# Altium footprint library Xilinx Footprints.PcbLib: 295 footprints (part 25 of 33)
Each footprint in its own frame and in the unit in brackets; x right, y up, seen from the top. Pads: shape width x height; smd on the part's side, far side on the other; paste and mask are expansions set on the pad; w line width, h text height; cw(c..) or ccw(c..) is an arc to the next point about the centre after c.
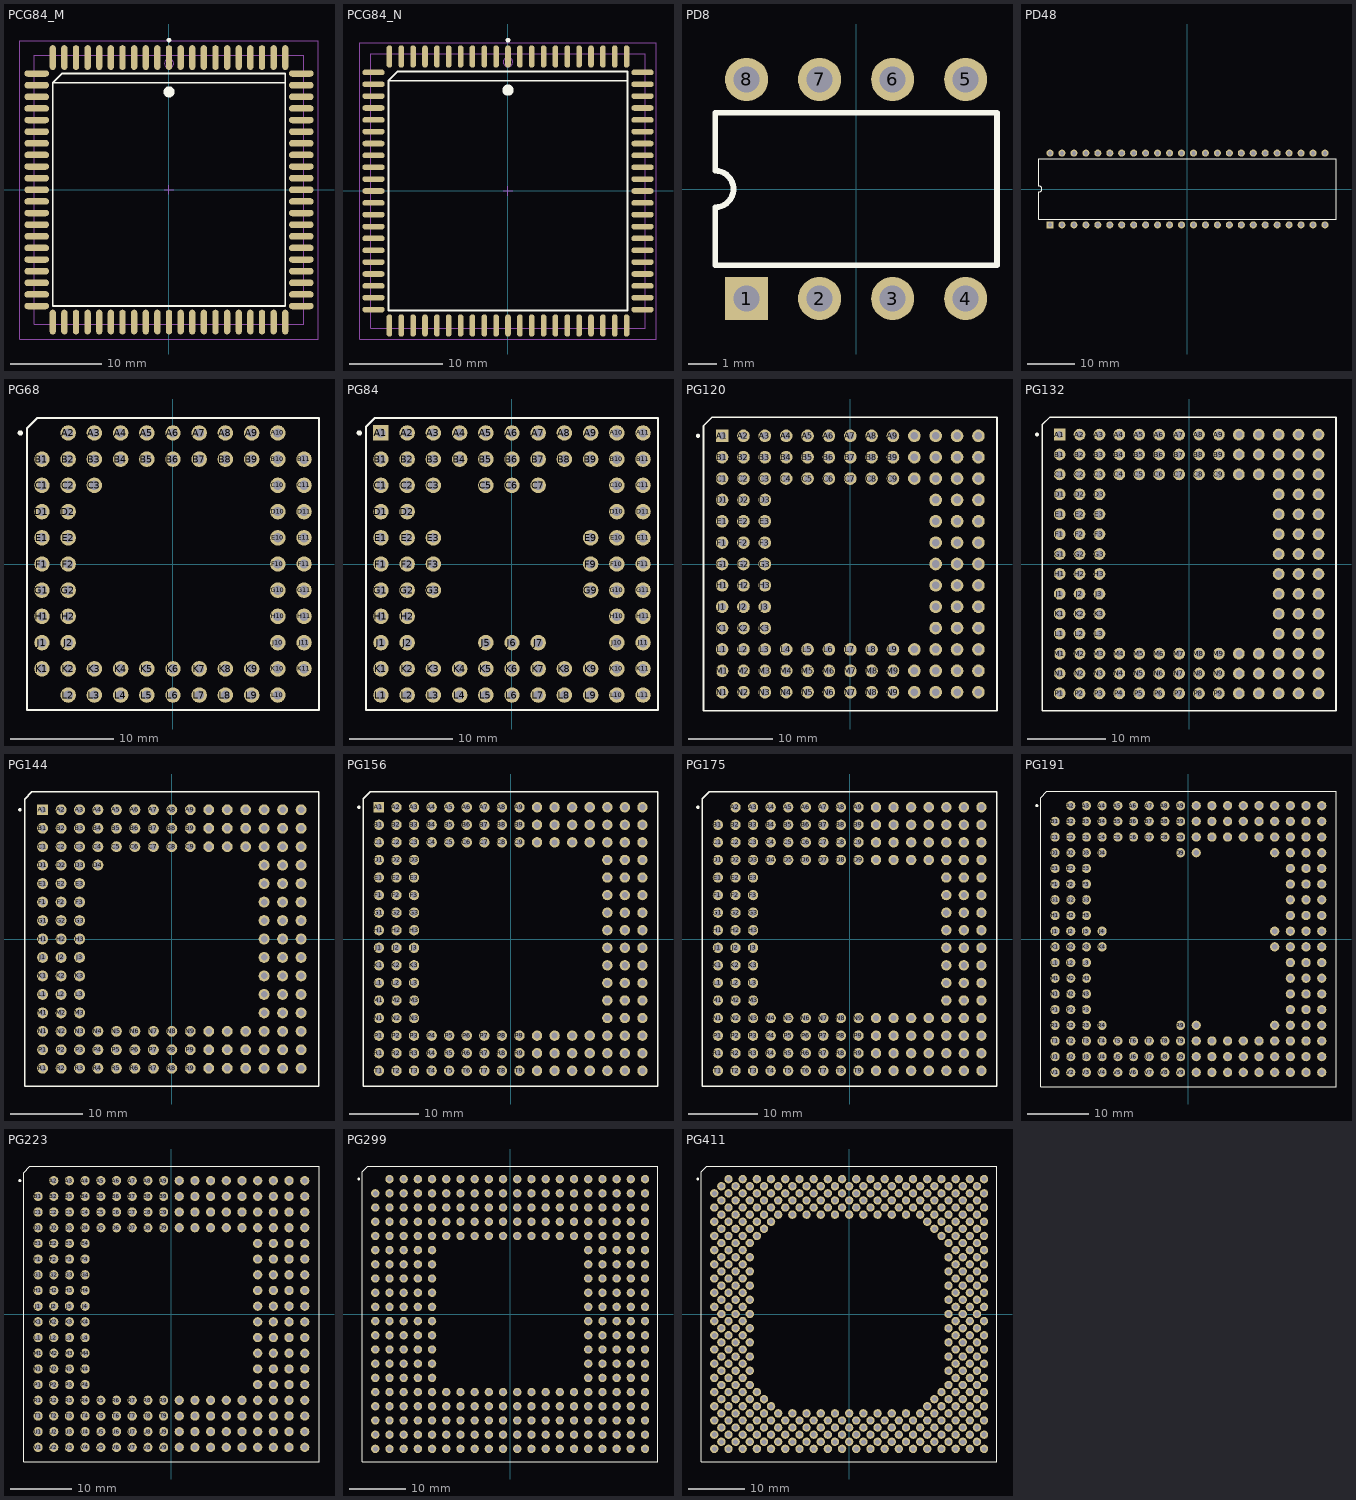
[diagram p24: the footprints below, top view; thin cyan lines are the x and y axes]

## PCG84_M [mm] "84-Pin Plastic Leaded Chip Carrier (PCG84) - Pb-Free, IPC Low Density"
height 5.08
pads (84):
  oval 0.7x2.7 smd: 1(0,14.45) 2(-1.27,14.45) 3(-2.54,14.45) 4(-3.81,14.45) 5(-5.08,14.45) 6(-6.35,14.45) 7(-7.62,14.45) 8(-8.89,14.45) 9(-10.16,14.45) 10(-11.43,14.45) 11(-12.7,14.45) 33(-12.7,-14.45) 34(-11.43,-14.45) 35(-10.16,-14.45) 36(-8.89,-14.45) 37(-7.62,-14.45) 38(-6.35,-14.45) 39(-5.08,-14.45) 40(-3.81,-14.45) 41(-2.54,-14.45) 42(-1.27,-14.45) 43(0,-14.45) 44(1.27,-14.45) 45(2.54,-14.45) 46(3.81,-14.45) 47(5.08,-14.45) 48(6.35,-14.45) 49(7.62,-14.45) 50(8.89,-14.45) 51(10.16,-14.45) 52(11.43,-14.45) 53(12.7,-14.45) 75(12.7,14.45) 76(11.43,14.45) 77(10.16,14.45) 78(8.89,14.45) 79(7.62,14.45) 80(6.35,14.45) 81(5.08,14.45) 82(3.81,14.45) 83(2.54,14.45) 84(1.27,14.45)
  oval 2.7x0.7 smd: 12(-14.45,12.7) 13(-14.45,11.43) 14(-14.45,10.16) 15(-14.45,8.89) 16(-14.45,7.62) 17(-14.45,6.35) 18(-14.45,5.08) 19(-14.45,3.81) 20(-14.45,2.54) 21(-14.45,1.27) 22(-14.45,0) 23(-14.45,-1.27) 24(-14.45,-2.54) 25(-14.45,-3.81) 26(-14.45,-5.08) 27(-14.45,-6.35) 28(-14.45,-7.62) 29(-14.45,-8.89) 30(-14.45,-10.16) 31(-14.45,-11.43) 32(-14.45,-12.7) 54(14.45,-12.7) 55(14.45,-11.43) 56(14.45,-10.16) 57(14.45,-8.89) 58(14.45,-7.62) 59(14.45,-6.35) 60(14.45,-5.08) 61(14.45,-3.81) 62(14.45,-2.54) 63(14.45,-1.27) 64(14.45,0) 65(14.45,1.27) 66(14.45,2.54) 67(14.45,3.81) 68(14.45,5.08) 69(14.45,6.35) 70(14.45,7.62) 71(14.45,8.89) 72(14.45,10.16) 73(14.45,11.43) 74(14.45,12.7)
Top Overlay:
  circle w0.25: c0,16.35 r0.125
  circle w0.6: c0,10.7 r0.3
  lines w0.2: 12.7,11.7 -12.7,11.7 ; -12.7,11.7 -11.7,12.7 12.7,12.7 12.7,-12.7 -12.7,-12.7 -12.7,11.7
Mechanical 13:
  circle w0.1: c0,13.805 r0.5
  lines w0.1: -14.705,-14.705 -14.705,14.705 14.705,14.705 14.705,-14.705 -14.705,-14.705
Mechanical 15:
  lines w0.1: -0.5,0 0.5,0 ; 0,-0.5 0,0.5 ; -16.3,-16.3 -16.3,16.3 16.3,16.3 16.3,-16.3 -16.3,-16.3
3D body: height 5.08, standoff 0, extent -14.705,-14.705 14.705,14.705

## PCG84_N [mm] "84-Pin Plastic Leaded Chip Carrier (PCG84) - Pb-Free, IPC Medium Density"
height 5.08
pads (84):
  oval 0.6x2.4 smd: 1(0,14.4) 2(-1.27,14.4) 3(-2.54,14.4) 4(-3.81,14.4) 5(-5.08,14.4) 6(-6.35,14.4) 7(-7.62,14.4) 8(-8.89,14.4) 9(-10.16,14.4) 10(-11.43,14.4) 11(-12.7,14.4) 33(-12.7,-14.4) 34(-11.43,-14.4) 35(-10.16,-14.4) 36(-8.89,-14.4) 37(-7.62,-14.4) 38(-6.35,-14.4) 39(-5.08,-14.4) 40(-3.81,-14.4) 41(-2.54,-14.4) 42(-1.27,-14.4) 43(0,-14.4) 44(1.27,-14.4) 45(2.54,-14.4) 46(3.81,-14.4) 47(5.08,-14.4) 48(6.35,-14.4) 49(7.62,-14.4) 50(8.89,-14.4) 51(10.16,-14.4) 52(11.43,-14.4) 53(12.7,-14.4) 75(12.7,14.4) 76(11.43,14.4) 77(10.16,14.4) 78(8.89,14.4) 79(7.62,14.4) 80(6.35,14.4) 81(5.08,14.4) 82(3.81,14.4) 83(2.54,14.4) 84(1.27,14.4)
  oval 2.4x0.6 smd: 12(-14.4,12.7) 13(-14.4,11.43) 14(-14.4,10.16) 15(-14.4,8.89) 16(-14.4,7.62) 17(-14.4,6.35) 18(-14.4,5.08) 19(-14.4,3.81) 20(-14.4,2.54) 21(-14.4,1.27) 22(-14.4,0) 23(-14.4,-1.27) 24(-14.4,-2.54) 25(-14.4,-3.81) 26(-14.4,-5.08) 27(-14.4,-6.35) 28(-14.4,-7.62) 29(-14.4,-8.89) 30(-14.4,-10.16) 31(-14.4,-11.43) 32(-14.4,-12.7) 54(14.4,-12.7) 55(14.4,-11.43) 56(14.4,-10.16) 57(14.4,-8.89) 58(14.4,-7.62) 59(14.4,-6.35) 60(14.4,-5.08) 61(14.4,-3.81) 62(14.4,-2.54) 63(14.4,-1.27) 64(14.4,0) 65(14.4,1.27) 66(14.4,2.54) 67(14.4,3.81) 68(14.4,5.08) 69(14.4,6.35) 70(14.4,7.62) 71(14.4,8.89) 72(14.4,10.16) 73(14.4,11.43) 74(14.4,12.7)
Top Overlay:
  circle w0.25: c0,16.15 r0.125
  circle w0.6: c0,10.8 r0.3
  lines w0.2: 12.8,11.8 -12.8,11.8 ; -12.8,11.8 -11.8,12.8 12.8,12.8 12.8,-12.8 -12.8,-12.8 -12.8,11.8
Mechanical 13:
  circle w0.1: c0,13.805 r0.5
  lines w0.1: -14.705,-14.705 -14.705,14.705 14.705,14.705 14.705,-14.705 -14.705,-14.705
Mechanical 15:
  lines w0.1: -0.5,0 0.5,0 ; 0,-0.5 0,0.5 ; -15.85,-15.85 -15.85,15.85 15.85,15.85 15.85,-15.85 -15.85,-15.85
3D body: height 5.08, standoff 0, extent -14.705,-14.705 14.705,14.705

## PD8 [mm] "8-Pin Plastic DIP (PD8)"
height 4.6
pads (8):
  rect 1.5x1.5 hole 0.9: 1(-3.81,-3.81)
  round 1.5 hole 0.9: 2(-1.27,-3.81) 3(1.27,-3.81) 4(3.81,-3.81) 5(3.81,3.81) 6(1.27,3.81) 7(-1.27,3.81) 8(-3.81,3.81)
Top Overlay:
  lines w0.2: -4.9,-2.65 -4.9,-0.635 ccw(c-4.9,0) -4.9,0.635 -4.9,2.65 4.9,2.65 4.9,-2.65 -4.9,-2.65

## PD48 [mm] "48-Pin Plastic DIP (PD48)"
height 4.83
pads (48):
  rect 1.5x1.5 hole 0.9: 1(-29.21,-7.62)
  round 1.5 hole 0.9: 2(-26.67,-7.62) 3(-24.13,-7.62) 4(-21.59,-7.62) 5(-19.05,-7.62) 6(-16.51,-7.62) 7(-13.97,-7.62) 8(-11.43,-7.62) 9(-8.89,-7.62) 10(-6.35,-7.62) 11(-3.81,-7.62) 12(-1.27,-7.62) 13(1.27,-7.62) 14(3.81,-7.62) 15(6.35,-7.62) 16(8.89,-7.62) 17(11.43,-7.62) 18(13.97,-7.62) 19(16.51,-7.62) 20(19.05,-7.62) 21(21.59,-7.62) 22(24.13,-7.62) 23(26.67,-7.62) 24(29.21,-7.62) 25(29.21,7.62) 26(26.67,7.62) 27(24.13,7.62) 28(21.59,7.62) 29(19.05,7.62) 30(16.51,7.62) 31(13.97,7.62) 32(11.43,7.62) 33(8.89,7.62) 34(6.35,7.62) 35(3.81,7.62) 36(1.27,7.62) 37(-1.27,7.62) 38(-3.81,7.62) 39(-6.35,7.62) 40(-8.89,7.62) 41(-11.43,7.62) 42(-13.97,7.62) 43(-16.51,7.62) 44(-19.05,7.62) 45(-21.59,7.62) 46(-24.13,7.62) 47(-26.67,7.62) 48(-29.21,7.62)
Top Overlay:
  lines w0.2: -31.55,-6.45 31.55,-6.45 31.55,6.45 -31.55,6.45 -31.55,0.635 cw(c-31.55,0) -31.55,-0.635 -31.55,-6.45

## PG68 [mm] "68-Pin Ceramic Pin Grid Array (PG68)"
height 5.21
pads (69):
  round 1.5 hole 0.9: A2(-10.16,12.7) A3(-7.62,12.7) A4(-5.08,12.7) A5(-2.54,12.7) A6(0,12.7) A7(2.54,12.7) A8(5.08,12.7) A9(7.62,12.7) A10(10.16,12.7) B1(-12.7,10.16) B2(-10.16,10.16) B3(-7.62,10.16) B4(-5.08,10.16) B5(-2.54,10.16) B6(0,10.16) B7(2.54,10.16) B8(5.08,10.16) B9(7.62,10.16) B10(10.16,10.16) B11(12.7,10.16) C1(-12.7,7.62) C2(-10.16,7.62) C3(-7.62,7.62) C10(10.16,7.62) C11(12.7,7.62) D1(-12.7,5.08) D2(-10.16,5.08) D10(10.16,5.08) D11(12.7,5.08) E1(-12.7,2.54) E2(-10.16,2.54) E10(10.16,2.54) E11(12.7,2.54) F1(-12.7,0) F2(-10.16,0) F10(10.16,0) F11(12.7,0) G1(-12.7,-2.54) G2(-10.16,-2.54) G10(10.16,-2.54) G11(12.7,-2.54) H1(-12.7,-5.08) H2(-10.16,-5.08) H10(10.16,-5.08) H11(12.7,-5.08) J1(-12.7,-7.62) J2(-10.16,-7.62) J10(10.16,-7.62) J11(12.7,-7.62) K1(-12.7,-10.16) K2(-10.16,-10.16) K3(-7.62,-10.16) K4(-5.08,-10.16) K5(-2.54,-10.16) K6(0,-10.16) K7(2.54,-10.16) K8(5.08,-10.16) K9(7.62,-10.16) K10(10.16,-10.16) K11(12.7,-10.16) L2(-10.16,-12.7) L3(-7.62,-12.7) L4(-5.08,-12.7) L5(-2.54,-12.7) L6(0,-12.7) L7(2.54,-12.7) L8(5.08,-12.7) L9(7.62,-12.7) L10(10.16,-12.7)
Top Overlay:
  circle w0.25: c-14.8,12.7 r0.125
  lines w0.2: -14.15,-14.15 -14.15,13.15 -13.15,14.15 14.15,14.15 14.15,-14.15 -14.15,-14.15

## PG84 [mm] "84-Pin Ceramic Pin Grid Array (PG84)"
height 5.21
pads (85):
  rect 1.5x1.5 hole 0.9: A1(-12.7,12.7)
  round 1.5 hole 0.9: A2(-10.16,12.7) A3(-7.62,12.7) A4(-5.08,12.7) A5(-2.54,12.7) A6(0,12.7) A7(2.54,12.7) A8(5.08,12.7) A9(7.62,12.7) A10(10.16,12.7) A11(12.7,12.7) B1(-12.7,10.16) B2(-10.16,10.16) B3(-7.62,10.16) B4(-5.08,10.16) B5(-2.54,10.16) B6(0,10.16) B7(2.54,10.16) B8(5.08,10.16) B9(7.62,10.16) B10(10.16,10.16) B11(12.7,10.16) C1(-12.7,7.62) C2(-10.16,7.62) C3(-7.62,7.62) C5(-2.54,7.62) C6(0,7.62) C7(2.54,7.62) C10(10.16,7.62) C11(12.7,7.62) D1(-12.7,5.08) D2(-10.16,5.08) D10(10.16,5.08) D11(12.7,5.08) E1(-12.7,2.54) E2(-10.16,2.54) E3(-7.62,2.54) E9(7.62,2.54) E10(10.16,2.54) E11(12.7,2.54) F1(-12.7,0) F2(-10.16,0) F3(-7.62,0) F9(7.62,0) F10(10.16,0) F11(12.7,0) G1(-12.7,-2.54) G2(-10.16,-2.54) G3(-7.62,-2.54) G9(7.62,-2.54) G10(10.16,-2.54) G11(12.7,-2.54) H1(-12.7,-5.08) H2(-10.16,-5.08) H10(10.16,-5.08) H11(12.7,-5.08) J1(-12.7,-7.62) J2(-10.16,-7.62) J5(-2.54,-7.62) J6(0,-7.62) J7(2.54,-7.62) J10(10.16,-7.62) J11(12.7,-7.62) K1(-12.7,-10.16) K2(-10.16,-10.16) K3(-7.62,-10.16) K4(-5.08,-10.16) K5(-2.54,-10.16) K6(0,-10.16) K7(2.54,-10.16) K8(5.08,-10.16) K9(7.62,-10.16) K10(10.16,-10.16) K11(12.7,-10.16) L1(-12.7,-12.7) L2(-10.16,-12.7) L3(-7.62,-12.7) L4(-5.08,-12.7) L5(-2.54,-12.7) L6(0,-12.7) L7(2.54,-12.7) L8(5.08,-12.7) L9(7.62,-12.7) L10(10.16,-12.7) L11(12.7,-12.7)
Top Overlay:
  circle w0.25: c-14.8,12.7 r0.125
  lines w0.2: -14.15,-14.15 -14.15,13.316 -13.316,14.15 14.15,14.15 14.15,-14.15 -14.15,-14.15

## PG120 [mm] "120-Pin Ceramic Pin Grid Array (PG120)"
height 5.21
pads (120):
  rect 1.5x1.5 hole 0.9: A1(-15.24,15.24)
  round 1.5 hole 0.9: A2(-12.7,15.24) A3(-10.16,15.24) A4(-7.62,15.24) A5(-5.08,15.24) A6(-2.54,15.24) A7(0,15.24) A8(2.54,15.24) A9(5.08,15.24) A10(7.62,15.24) A11(10.16,15.24) A12(12.7,15.24) A13(15.24,15.24) B1(-15.24,12.7) B2(-12.7,12.7) B3(-10.16,12.7) B4(-7.62,12.7) B5(-5.08,12.7) B6(-2.54,12.7) B7(0,12.7) B8(2.54,12.7) B9(5.08,12.7) B10(7.62,12.7) B11(10.16,12.7) B12(12.7,12.7) B13(15.24,12.7) C1(-15.24,10.16) C2(-12.7,10.16) C3(-10.16,10.16) C4(-7.62,10.16) C5(-5.08,10.16) C6(-2.54,10.16) C7(0,10.16) C8(2.54,10.16) C9(5.08,10.16) C10(7.62,10.16) C11(10.16,10.16) C12(12.7,10.16) C13(15.24,10.16) D1(-15.24,7.62) D2(-12.7,7.62) D3(-10.16,7.62) D11(10.16,7.62) D12(12.7,7.62) D13(15.24,7.62) E1(-15.24,5.08) E2(-12.7,5.08) E3(-10.16,5.08) E11(10.16,5.08) E12(12.7,5.08) E13(15.24,5.08) F1(-15.24,2.54) F2(-12.7,2.54) F3(-10.16,2.54) F11(10.16,2.54) F12(12.7,2.54) F13(15.24,2.54) G1(-15.24,0) G2(-12.7,0) G3(-10.16,0) G11(10.16,0) G12(12.7,0) G13(15.24,0) H1(-15.24,-2.54) H2(-12.7,-2.54) H3(-10.16,-2.54) H11(10.16,-2.54) H12(12.7,-2.54) H13(15.24,-2.54) J1(-15.24,-5.08) J2(-12.7,-5.08) J3(-10.16,-5.08) J11(10.16,-5.08) J12(12.7,-5.08) J13(15.24,-5.08) K1(-15.24,-7.62) K2(-12.7,-7.62) K3(-10.16,-7.62) K11(10.16,-7.62) K12(12.7,-7.62) K13(15.24,-7.62) L1(-15.24,-10.16) L2(-12.7,-10.16) L3(-10.16,-10.16) L4(-7.62,-10.16) L5(-5.08,-10.16) L6(-2.54,-10.16) L7(0,-10.16) L8(2.54,-10.16) L9(5.08,-10.16) L10(7.62,-10.16) L11(10.16,-10.16) L12(12.7,-10.16) L13(15.24,-10.16) M1(-15.24,-12.7) M2(-12.7,-12.7) M3(-10.16,-12.7) M4(-7.62,-12.7) M5(-5.08,-12.7) M6(-2.54,-12.7) M7(0,-12.7) M8(2.54,-12.7) M9(5.08,-12.7) M10(7.62,-12.7) M11(10.16,-12.7) M12(12.7,-12.7) M13(15.24,-12.7) N1(-15.24,-15.24) N2(-12.7,-15.24) N3(-10.16,-15.24) N4(-7.62,-15.24) N5(-5.08,-15.24) N6(-2.54,-15.24) N7(0,-15.24) N8(2.54,-15.24) N9(5.08,-15.24) N10(7.62,-15.24) N11(10.16,-15.24) N12(12.7,-15.24) N13(15.24,-15.24)
Top Overlay:
  circle w0.25: c-18.1,15.24 r0.125
  lines w0.2: -17.45,-17.45 17.45,-17.45 17.45,17.45 -16.45,17.45 -17.45,16.45 -17.45,-17.45

## PG132 [mm] "132-Pin Ceramic Pin Grid Array (PG132)"
height 5.21
pads (132):
  rect 1.5x1.5 hole 0.9: A1(-16.51,16.51)
  round 1.5 hole 0.9: A2(-13.97,16.51) A3(-11.43,16.51) A4(-8.89,16.51) A5(-6.35,16.51) A6(-3.81,16.51) A7(-1.27,16.51) A8(1.27,16.51) A9(3.81,16.51) A10(6.35,16.51) A11(8.89,16.51) A12(11.43,16.51) A13(13.97,16.51) A14(16.51,16.51) B1(-16.51,13.97) B2(-13.97,13.97) B3(-11.43,13.97) B4(-8.89,13.97) B5(-6.35,13.97) B6(-3.81,13.97) B7(-1.27,13.97) B8(1.27,13.97) B9(3.81,13.97) B10(6.35,13.97) B11(8.89,13.97) B12(11.43,13.97) B13(13.97,13.97) B14(16.51,13.97) C1(-16.51,11.43) C2(-13.97,11.43) C3(-11.43,11.43) C4(-8.89,11.43) C5(-6.35,11.43) C6(-3.81,11.43) C7(-1.27,11.43) C8(1.27,11.43) C9(3.81,11.43) C10(6.35,11.43) C11(8.89,11.43) C12(11.43,11.43) C13(13.97,11.43) C14(16.51,11.43) D1(-16.51,8.89) D2(-13.97,8.89) D3(-11.43,8.89) D12(11.43,8.89) D13(13.97,8.89) D14(16.51,8.89) E1(-16.51,6.35) E2(-13.97,6.35) E3(-11.43,6.35) E12(11.43,6.35) E13(13.97,6.35) E14(16.51,6.35) F1(-16.51,3.81) F2(-13.97,3.81) F3(-11.43,3.81) F12(11.43,3.81) F13(13.97,3.81) F14(16.51,3.81) G1(-16.51,1.27) G2(-13.97,1.27) G3(-11.43,1.27) G12(11.43,1.27) G13(13.97,1.27) G14(16.51,1.27) H1(-16.51,-1.27) H2(-13.97,-1.27) H3(-11.43,-1.27) H12(11.43,-1.27) H13(13.97,-1.27) H14(16.51,-1.27) J1(-16.51,-3.81) J2(-13.97,-3.81) J3(-11.43,-3.81) J12(11.43,-3.81) J13(13.97,-3.81) J14(16.51,-3.81) K1(-16.51,-6.35) K2(-13.97,-6.35) K3(-11.43,-6.35) K12(11.43,-6.35) K13(13.97,-6.35) K14(16.51,-6.35) L1(-16.51,-8.89) L2(-13.97,-8.89) L3(-11.43,-8.89) L12(11.43,-8.89) L13(13.97,-8.89) L14(16.51,-8.89) M1(-16.51,-11.43) M2(-13.97,-11.43) M3(-11.43,-11.43) M4(-8.89,-11.43) M5(-6.35,-11.43) M6(-3.81,-11.43) M7(-1.27,-11.43) M8(1.27,-11.43) M9(3.81,-11.43) M10(6.35,-11.43) M11(8.89,-11.43) M12(11.43,-11.43) M13(13.97,-11.43) M14(16.51,-11.43) N1(-16.51,-13.97) N2(-13.97,-13.97) N3(-11.43,-13.97) N4(-8.89,-13.97) N5(-6.35,-13.97) N6(-3.81,-13.97) N7(-1.27,-13.97) N8(1.27,-13.97) N9(3.81,-13.97) N10(6.35,-13.97) N11(8.89,-13.97) N12(11.43,-13.97) N13(13.97,-13.97) N14(16.51,-13.97) P1(-16.51,-16.51) P2(-13.97,-16.51) P3(-11.43,-16.51) P4(-8.89,-16.51) P5(-6.35,-16.51) P6(-3.81,-16.51) P7(-1.27,-16.51) P8(1.27,-16.51) P9(3.81,-16.51) P10(6.35,-16.51) P11(8.89,-16.51) P12(11.43,-16.51) P13(13.97,-16.51) P14(16.51,-16.51)
Top Overlay:
  circle w0.25: c-19.4,16.51 r0.125
  lines w0.2: -18.75,-18.75 -18.75,17.75 -17.75,18.75 18.75,18.75 18.75,-18.75 -18.75,-18.75

## PG144 [mm] "144-Pin Ceramic Pin Grid Array (PG144)"
height 4.93
pads (145):
  rect 1.5x1.5 hole 0.9: A1(-17.78,17.78)
  round 1.5 hole 0.9: A2(-15.24,17.78) A3(-12.7,17.78) A4(-10.16,17.78) A5(-7.62,17.78) A6(-5.08,17.78) A7(-2.54,17.78) A8(0,17.78) A9(2.54,17.78) A10(5.08,17.78) A11(7.62,17.78) A12(10.16,17.78) A13(12.7,17.78) A14(15.24,17.78) A15(17.78,17.78) B1(-17.78,15.24) B2(-15.24,15.24) B3(-12.7,15.24) B4(-10.16,15.24) B5(-7.62,15.24) B6(-5.08,15.24) B7(-2.54,15.24) B8(0,15.24) B9(2.54,15.24) B10(5.08,15.24) B11(7.62,15.24) B12(10.16,15.24) B13(12.7,15.24) B14(15.24,15.24) B15(17.78,15.24) C1(-17.78,12.7) C2(-15.24,12.7) C3(-12.7,12.7) C4(-10.16,12.7) C5(-7.62,12.7) C6(-5.08,12.7) C7(-2.54,12.7) C8(0,12.7) C9(2.54,12.7) C10(5.08,12.7) C11(7.62,12.7) C12(10.16,12.7) C13(12.7,12.7) C14(15.24,12.7) C15(17.78,12.7) D1(-17.78,10.16) D2(-15.24,10.16) D3(-12.7,10.16) D4(-10.16,10.16) D13(12.7,10.16) D14(15.24,10.16) D15(17.78,10.16) E1(-17.78,7.62) E2(-15.24,7.62) E3(-12.7,7.62) E13(12.7,7.62) E14(15.24,7.62) E15(17.78,7.62) F1(-17.78,5.08) F2(-15.24,5.08) F3(-12.7,5.08) F13(12.7,5.08) F14(15.24,5.08) F15(17.78,5.08) G1(-17.78,2.54) G2(-15.24,2.54) G3(-12.7,2.54) G13(12.7,2.54) G14(15.24,2.54) G15(17.78,2.54) H1(-17.78,0) H2(-15.24,0) H3(-12.7,0) H13(12.7,0) H14(15.24,0) H15(17.78,0) J1(-17.78,-2.54) J2(-15.24,-2.54) J3(-12.7,-2.54) J13(12.7,-2.54) J14(15.24,-2.54) J15(17.78,-2.54) K1(-17.78,-5.08) K2(-15.24,-5.08) K3(-12.7,-5.08) K13(12.7,-5.08) K14(15.24,-5.08) K15(17.78,-5.08) L1(-17.78,-7.62) L2(-15.24,-7.62) L3(-12.7,-7.62) L13(12.7,-7.62) L14(15.24,-7.62) L15(17.78,-7.62) M1(-17.78,-10.16) M2(-15.24,-10.16) M3(-12.7,-10.16) M13(12.7,-10.16) M14(15.24,-10.16) M15(17.78,-10.16) N1(-17.78,-12.7) N2(-15.24,-12.7) N3(-12.7,-12.7) N4(-10.16,-12.7) N5(-7.62,-12.7) N6(-5.08,-12.7) N7(-2.54,-12.7) N8(0,-12.7) N9(2.54,-12.7) N10(5.08,-12.7) N11(7.62,-12.7) N12(10.16,-12.7) N13(12.7,-12.7) N14(15.24,-12.7) N15(17.78,-12.7) P1(-17.78,-15.24) P2(-15.24,-15.24) P3(-12.7,-15.24) P4(-10.16,-15.24) P5(-7.62,-15.24) P6(-5.08,-15.24) P7(-2.54,-15.24) P8(0,-15.24) P9(2.54,-15.24) P10(5.08,-15.24) P11(7.62,-15.24) P12(10.16,-15.24) P13(12.7,-15.24) P14(15.24,-15.24) P15(17.78,-15.24) R1(-17.78,-17.78) R2(-15.24,-17.78) R3(-12.7,-17.78) R4(-10.16,-17.78) R5(-7.62,-17.78) R6(-5.08,-17.78) R7(-2.54,-17.78) R8(0,-17.78) R9(2.54,-17.78) R10(5.08,-17.78) R11(7.62,-17.78) R12(10.16,-17.78) R13(12.7,-17.78) R14(15.24,-17.78) R15(17.78,-17.78)
Top Overlay:
  circle w0.25: c-20.9,17.78 r0.125
  lines w0.2: -20.25,-20.25 20.25,-20.25 20.25,20.25 -19.25,20.25 -20.25,19.25 -20.25,-20.25

## PG156 [mm] "156-Pin Ceramic Pin Grid Array (PG156)"
height 3.94
pads (156):
  rect 1.5x1.5 hole 0.9: A1(-19.05,19.05)
  round 1.5 hole 0.9: A2(-16.51,19.05) A3(-13.97,19.05) A4(-11.43,19.05) A5(-8.89,19.05) A6(-6.35,19.05) A7(-3.81,19.05) A8(-1.27,19.05) A9(1.27,19.05) A10(3.81,19.05) A11(6.35,19.05) A12(8.89,19.05) A13(11.43,19.05) A14(13.97,19.05) A15(16.51,19.05) A16(19.05,19.05) B1(-19.05,16.51) B2(-16.51,16.51) B3(-13.97,16.51) B4(-11.43,16.51) B5(-8.89,16.51) B6(-6.35,16.51) B7(-3.81,16.51) B8(-1.27,16.51) B9(1.27,16.51) B10(3.81,16.51) B11(6.35,16.51) B12(8.89,16.51) B13(11.43,16.51) B14(13.97,16.51) B15(16.51,16.51) B16(19.05,16.51) C1(-19.05,13.97) C2(-16.51,13.97) C3(-13.97,13.97) C4(-11.43,13.97) C5(-8.89,13.97) C6(-6.35,13.97) C7(-3.81,13.97) C8(-1.27,13.97) C9(1.27,13.97) C10(3.81,13.97) C11(6.35,13.97) C12(8.89,13.97) C13(11.43,13.97) C14(13.97,13.97) C15(16.51,13.97) C16(19.05,13.97) D1(-19.05,11.43) D2(-16.51,11.43) D3(-13.97,11.43) D14(13.97,11.43) D15(16.51,11.43) D16(19.05,11.43) E1(-19.05,8.89) E2(-16.51,8.89) E3(-13.97,8.89) E14(13.97,8.89) E15(16.51,8.89) E16(19.05,8.89) F1(-19.05,6.35) F2(-16.51,6.35) F3(-13.97,6.35) F14(13.97,6.35) F15(16.51,6.35) F16(19.05,6.35) G1(-19.05,3.81) G2(-16.51,3.81) G3(-13.97,3.81) G14(13.97,3.81) G15(16.51,3.81) G16(19.05,3.81) H1(-19.05,1.27) H2(-16.51,1.27) H3(-13.97,1.27) H14(13.97,1.27) H15(16.51,1.27) H16(19.05,1.27) J1(-19.05,-1.27) J2(-16.51,-1.27) J3(-13.97,-1.27) J14(13.97,-1.27) J15(16.51,-1.27) J16(19.05,-1.27) K1(-19.05,-3.81) K2(-16.51,-3.81) K3(-13.97,-3.81) K14(13.97,-3.81) K15(16.51,-3.81) K16(19.05,-3.81) L1(-19.05,-6.35) L2(-16.51,-6.35) L3(-13.97,-6.35) L14(13.97,-6.35) L15(16.51,-6.35) L16(19.05,-6.35) M1(-19.05,-8.89) M2(-16.51,-8.89) M3(-13.97,-8.89) M14(13.97,-8.89) M15(16.51,-8.89) M16(19.05,-8.89) N1(-19.05,-11.43) N2(-16.51,-11.43) N3(-13.97,-11.43) N14(13.97,-11.43) N15(16.51,-11.43) N16(19.05,-11.43) P1(-19.05,-13.97) P2(-16.51,-13.97) P3(-13.97,-13.97) P4(-11.43,-13.97) P5(-8.89,-13.97) P6(-6.35,-13.97) P7(-3.81,-13.97) P8(-1.27,-13.97) P9(1.27,-13.97) P10(3.81,-13.97) P11(6.35,-13.97) P12(8.89,-13.97) P13(11.43,-13.97) P14(13.97,-13.97) P15(16.51,-13.97) P16(19.05,-13.97) R1(-19.05,-16.51) R2(-16.51,-16.51) R3(-13.97,-16.51) R4(-11.43,-16.51) R5(-8.89,-16.51) R6(-6.35,-16.51) R7(-3.81,-16.51) R8(-1.27,-16.51) R9(1.27,-16.51) R10(3.81,-16.51) R11(6.35,-16.51) R12(8.89,-16.51) R13(11.43,-16.51) R14(13.97,-16.51) R15(16.51,-16.51) R16(19.05,-16.51) T1(-19.05,-19.05) T2(-16.51,-19.05) T3(-13.97,-19.05) T4(-11.43,-19.05) T5(-8.89,-19.05) T6(-6.35,-19.05) T7(-3.81,-19.05) T8(-1.27,-19.05) T9(1.27,-19.05) T10(3.81,-19.05) T11(6.35,-19.05) T12(8.89,-19.05) T13(11.43,-19.05) T14(13.97,-19.05) T15(16.51,-19.05) T16(19.05,-19.05)
Top Overlay:
  circle w0.25: c-21.95,19.05 r0.125
  lines w0.2: -21.3,-21.3 21.3,-21.3 21.3,21.3 -20.3,21.3 -21.3,20.3 -21.3,-21.3

## PG175 [mm] "175-Pin Ceramic Pin Grid Array (PG175)"
height 5.21
pads (175):
  round 1.5 hole 0.9: A2(-16.51,19.05) A3(-13.97,19.05) A4(-11.43,19.05) A5(-8.89,19.05) A6(-6.35,19.05) A7(-3.81,19.05) A8(-1.27,19.05) A9(1.27,19.05) A10(3.81,19.05) A11(6.35,19.05) A12(8.89,19.05) A13(11.43,19.05) A14(13.97,19.05) A15(16.51,19.05) A16(19.05,19.05) B1(-19.05,16.51) B2(-16.51,16.51) B3(-13.97,16.51) B4(-11.43,16.51) B5(-8.89,16.51) B6(-6.35,16.51) B7(-3.81,16.51) B8(-1.27,16.51) B9(1.27,16.51) B10(3.81,16.51) B11(6.35,16.51) B12(8.89,16.51) B13(11.43,16.51) B14(13.97,16.51) B15(16.51,16.51) B16(19.05,16.51) C1(-19.05,13.97) C2(-16.51,13.97) C3(-13.97,13.97) C4(-11.43,13.97) C5(-8.89,13.97) C6(-6.35,13.97) C7(-3.81,13.97) C8(-1.27,13.97) C9(1.27,13.97) C10(3.81,13.97) C11(6.35,13.97) C12(8.89,13.97) C13(11.43,13.97) C14(13.97,13.97) C15(16.51,13.97) C16(19.05,13.97) D1(-19.05,11.43) D2(-16.51,11.43) D3(-13.97,11.43) D4(-11.43,11.43) D5(-8.89,11.43) D6(-6.35,11.43) D7(-3.81,11.43) D8(-1.27,11.43) D9(1.27,11.43) D10(3.81,11.43) D11(6.35,11.43) D12(8.89,11.43) D13(11.43,11.43) D14(13.97,11.43) D15(16.51,11.43) D16(19.05,11.43) E1(-19.05,8.89) E2(-16.51,8.89) E3(-13.97,8.89) E14(13.97,8.89) E15(16.51,8.89) E16(19.05,8.89) F1(-19.05,6.35) F2(-16.51,6.35) F3(-13.97,6.35) F14(13.97,6.35) F15(16.51,6.35) F16(19.05,6.35) G1(-19.05,3.81) G2(-16.51,3.81) G3(-13.97,3.81) G14(13.97,3.81) G15(16.51,3.81) G16(19.05,3.81) H1(-19.05,1.27) H2(-16.51,1.27) H3(-13.97,1.27) H14(13.97,1.27) H15(16.51,1.27) H16(19.05,1.27) J1(-19.05,-1.27) J2(-16.51,-1.27) J3(-13.97,-1.27) J14(13.97,-1.27) J15(16.51,-1.27) J16(19.05,-1.27) K1(-19.05,-3.81) K2(-16.51,-3.81) K3(-13.97,-3.81) K14(13.97,-3.81) K15(16.51,-3.81) K16(19.05,-3.81) L1(-19.05,-6.35) L2(-16.51,-6.35) L3(-13.97,-6.35) L14(13.97,-6.35) L15(16.51,-6.35) L16(19.05,-6.35) M1(-19.05,-8.89) M2(-16.51,-8.89) M3(-13.97,-8.89) M14(13.97,-8.89) M15(16.51,-8.89) M16(19.05,-8.89) N1(-19.05,-11.43) N2(-16.51,-11.43) N3(-13.97,-11.43) N4(-11.43,-11.43) N5(-8.89,-11.43) N6(-6.35,-11.43) N7(-3.81,-11.43) N8(-1.27,-11.43) N9(1.27,-11.43) N10(3.81,-11.43) N11(6.35,-11.43) N12(8.89,-11.43) N13(11.43,-11.43) N14(13.97,-11.43) N15(16.51,-11.43) N16(19.05,-11.43) P1(-19.05,-13.97) P2(-16.51,-13.97) P3(-13.97,-13.97) P4(-11.43,-13.97) P5(-8.89,-13.97) P6(-6.35,-13.97) P7(-3.81,-13.97) P8(-1.27,-13.97) P9(1.27,-13.97) P10(3.81,-13.97) P11(6.35,-13.97) P12(8.89,-13.97) P13(11.43,-13.97) P14(13.97,-13.97) P15(16.51,-13.97) P16(19.05,-13.97) R1(-19.05,-16.51) R2(-16.51,-16.51) R3(-13.97,-16.51) R4(-11.43,-16.51) R5(-8.89,-16.51) R6(-6.35,-16.51) R7(-3.81,-16.51) R8(-1.27,-16.51) R9(1.27,-16.51) R10(3.81,-16.51) R11(6.35,-16.51) R12(8.89,-16.51) R13(11.43,-16.51) R14(13.97,-16.51) R15(16.51,-16.51) R16(19.05,-16.51) T1(-19.05,-19.05) T2(-16.51,-19.05) T3(-13.97,-19.05) T4(-11.43,-19.05) T5(-8.89,-19.05) T6(-6.35,-19.05) T7(-3.81,-19.05) T8(-1.27,-19.05) T9(1.27,-19.05) T10(3.81,-19.05) T11(6.35,-19.05) T12(8.89,-19.05) T13(11.43,-19.05) T14(13.97,-19.05) T15(16.51,-19.05) T16(19.05,-19.05)
Top Overlay:
  circle w0.25: c-21.95,19.05 r0.125
  lines w0.2: -21.3,-21.3 -21.3,20.3 -20.3,21.3 21.3,21.3 21.3,-21.3 -21.3,-21.3

## PG191 [mm] "191-Pin Ceramic Pin Grid Array (PG191)"
height 5.21
pads (191):
  round 1.5 hole 0.9: A2(-19.05,21.59) A3(-16.51,21.59) A4(-13.97,21.59) A5(-11.43,21.59) A6(-8.89,21.59) A7(-6.35,21.59) A8(-3.81,21.59) A9(-1.27,21.59) A10(1.27,21.59) A11(3.81,21.59) A12(6.35,21.59) A13(8.89,21.59) A14(11.43,21.59) A15(13.97,21.59) A16(16.51,21.59) A17(19.05,21.59) A18(21.59,21.59) B1(-21.59,19.05) B2(-19.05,19.05) B3(-16.51,19.05) B4(-13.97,19.05) B5(-11.43,19.05) B6(-8.89,19.05) B7(-6.35,19.05) B8(-3.81,19.05) B9(-1.27,19.05) B10(1.27,19.05) B11(3.81,19.05) B12(6.35,19.05) B13(8.89,19.05) B14(11.43,19.05) B15(13.97,19.05) B16(16.51,19.05) B17(19.05,19.05) B18(21.59,19.05) C1(-21.59,16.51) C2(-19.05,16.51) C3(-16.51,16.51) C4(-13.97,16.51) C5(-11.43,16.51) C6(-8.89,16.51) C7(-6.35,16.51) C8(-3.81,16.51) C9(-1.27,16.51) C10(1.27,16.51) C11(3.81,16.51) C12(6.35,16.51) C13(8.89,16.51) C14(11.43,16.51) C15(13.97,16.51) C16(16.51,16.51) C17(19.05,16.51) C18(21.59,16.51) D1(-21.59,13.97) D2(-19.05,13.97) D3(-16.51,13.97) D4(-13.97,13.97) D9(-1.27,13.97) D10(1.27,13.97) D15(13.97,13.97) D16(16.51,13.97) D17(19.05,13.97) D18(21.59,13.97) E1(-21.59,11.43) E2(-19.05,11.43) E3(-16.51,11.43) E16(16.51,11.43) E17(19.05,11.43) E18(21.59,11.43) F1(-21.59,8.89) F2(-19.05,8.89) F3(-16.51,8.89) F16(16.51,8.89) F17(19.05,8.89) F18(21.59,8.89) G1(-21.59,6.35) G2(-19.05,6.35) G3(-16.51,6.35) G16(16.51,6.35) G17(19.05,6.35) G18(21.59,6.35) H1(-21.59,3.81) H2(-19.05,3.81) H3(-16.51,3.81) H16(16.51,3.81) H17(19.05,3.81) H18(21.59,3.81) J1(-21.59,1.27) J2(-19.05,1.27) J3(-16.51,1.27) J4(-13.97,1.27) J15(13.97,1.27) J16(16.51,1.27) J17(19.05,1.27) J18(21.59,1.27) K1(-21.59,-1.27) K2(-19.05,-1.27) K3(-16.51,-1.27) K4(-13.97,-1.27) K15(13.97,-1.27) K16(16.51,-1.27) K17(19.05,-1.27) K18(21.59,-1.27) L1(-21.59,-3.81) L2(-19.05,-3.81) L3(-16.51,-3.81) L16(16.51,-3.81) L17(19.05,-3.81) L18(21.59,-3.81) M1(-21.59,-6.35) M2(-19.05,-6.35) M3(-16.51,-6.35) M16(16.51,-6.35) M17(19.05,-6.35) M18(21.59,-6.35) N1(-21.59,-8.89) N2(-19.05,-8.89) N3(-16.51,-8.89) N16(16.51,-8.89) N17(19.05,-8.89) N18(21.59,-8.89) P1(-21.59,-11.43) P2(-19.05,-11.43) P3(-16.51,-11.43) P16(16.51,-11.43) P17(19.05,-11.43) P18(21.59,-11.43) R1(-21.59,-13.97) R2(-19.05,-13.97) R3(-16.51,-13.97) R4(-13.97,-13.97) R9(-1.27,-13.97) R10(1.27,-13.97) R15(13.97,-13.97) R16(16.51,-13.97) R17(19.05,-13.97) R18(21.59,-13.97) T1(-21.59,-16.51) T2(-19.05,-16.51) T3(-16.51,-16.51) T4(-13.97,-16.51) T5(-11.43,-16.51) T6(-8.89,-16.51) T7(-6.35,-16.51) T8(-3.81,-16.51) T9(-1.27,-16.51) T10(1.27,-16.51) T11(3.81,-16.51) T12(6.35,-16.51) T13(8.89,-16.51) T14(11.43,-16.51) T15(13.97,-16.51) T16(16.51,-16.51) T17(19.05,-16.51) T18(21.59,-16.51) U1(-21.59,-19.05) U2(-19.05,-19.05) U3(-16.51,-19.05) U4(-13.97,-19.05) U5(-11.43,-19.05) U6(-8.89,-19.05) U7(-6.35,-19.05) U8(-3.81,-19.05) U9(-1.27,-19.05) U10(1.27,-19.05) U11(3.81,-19.05) U12(6.35,-19.05) U13(8.89,-19.05) U14(11.43,-19.05) U15(13.97,-19.05) U16(16.51,-19.05) U17(19.05,-19.05) U18(21.59,-19.05) V1(-21.59,-21.59) V2(-19.05,-21.59) V3(-16.51,-21.59) V4(-13.97,-21.59) V5(-11.43,-21.59) V6(-8.89,-21.59) V7(-6.35,-21.59) V8(-3.81,-21.59) V9(-1.27,-21.59) V10(1.27,-21.59) V11(3.81,-21.59) V12(6.35,-21.59) V13(8.89,-21.59) V14(11.43,-21.59) V15(13.97,-21.59) V16(16.51,-21.59) V17(19.05,-21.59) V18(21.59,-21.59)
Top Overlay:
  circle w0.25: c-24.55,21.59 r0.125
  lines w0.2: -23.9,-23.9 23.9,-23.9 23.9,23.9 -22.9,23.9 -23.9,22.9 -23.9,-23.9

## PG223 [mm] "223-Pin Ceramic Pin Grid Array (PG223)"
height 5.21
pads (223):
  round 1.5 hole 0.9: A2(-19.05,21.59) A3(-16.51,21.59) A4(-13.97,21.59) A5(-11.43,21.59) A6(-8.89,21.59) A7(-6.35,21.59) A8(-3.81,21.59) A9(-1.27,21.59) A10(1.27,21.59) A11(3.81,21.59) A12(6.35,21.59) A13(8.89,21.59) A14(11.43,21.59) A15(13.97,21.59) A16(16.51,21.59) A17(19.05,21.59) A18(21.59,21.59) B1(-21.59,19.05) B2(-19.05,19.05) B3(-16.51,19.05) B4(-13.97,19.05) B5(-11.43,19.05) B6(-8.89,19.05) B7(-6.35,19.05) B8(-3.81,19.05) B9(-1.27,19.05) B10(1.27,19.05) B11(3.81,19.05) B12(6.35,19.05) B13(8.89,19.05) B14(11.43,19.05) B15(13.97,19.05) B16(16.51,19.05) B17(19.05,19.05) B18(21.59,19.05) C1(-21.59,16.51) C2(-19.05,16.51) C3(-16.51,16.51) C4(-13.97,16.51) C5(-11.43,16.51) C6(-8.89,16.51) C7(-6.35,16.51) C8(-3.81,16.51) C9(-1.27,16.51) C10(1.27,16.51) C11(3.81,16.51) C12(6.35,16.51) C13(8.89,16.51) C14(11.43,16.51) C15(13.97,16.51) C16(16.51,16.51) C17(19.05,16.51) C18(21.59,16.51) D1(-21.59,13.97) D2(-19.05,13.97) D3(-16.51,13.97) D4(-13.97,13.97) D5(-11.43,13.97) D6(-8.89,13.97) D7(-6.35,13.97) D8(-3.81,13.97) D9(-1.27,13.97) D10(1.27,13.97) D11(3.81,13.97) D12(6.35,13.97) D13(8.89,13.97) D14(11.43,13.97) D15(13.97,13.97) D16(16.51,13.97) D17(19.05,13.97) D18(21.59,13.97) E1(-21.59,11.43) E2(-19.05,11.43) E3(-16.51,11.43) E4(-13.97,11.43) E15(13.97,11.43) E16(16.51,11.43) E17(19.05,11.43) E18(21.59,11.43) F1(-21.59,8.89) F2(-19.05,8.89) F3(-16.51,8.89) F4(-13.97,8.89) F15(13.97,8.89) F16(16.51,8.89) F17(19.05,8.89) F18(21.59,8.89) G1(-21.59,6.35) G2(-19.05,6.35) G3(-16.51,6.35) G4(-13.97,6.35) G15(13.97,6.35) G16(16.51,6.35) G17(19.05,6.35) G18(21.59,6.35) H1(-21.59,3.81) H2(-19.05,3.81) H3(-16.51,3.81) H4(-13.97,3.81) H15(13.97,3.81) H16(16.51,3.81) H17(19.05,3.81) H18(21.59,3.81) J1(-21.59,1.27) J2(-19.05,1.27) J3(-16.51,1.27) J4(-13.97,1.27) J15(13.97,1.27) J16(16.51,1.27) J17(19.05,1.27) J18(21.59,1.27) K1(-21.59,-1.27) K2(-19.05,-1.27) K3(-16.51,-1.27) K4(-13.97,-1.27) K15(13.97,-1.27) K16(16.51,-1.27) K17(19.05,-1.27) K18(21.59,-1.27) L1(-21.59,-3.81) L2(-19.05,-3.81) L3(-16.51,-3.81) L4(-13.97,-3.81) L15(13.97,-3.81) L16(16.51,-3.81) L17(19.05,-3.81) L18(21.59,-3.81) M1(-21.59,-6.35) M2(-19.05,-6.35) M3(-16.51,-6.35) M4(-13.97,-6.35) M15(13.97,-6.35) M16(16.51,-6.35) M17(19.05,-6.35) M18(21.59,-6.35) N1(-21.59,-8.89) N2(-19.05,-8.89) N3(-16.51,-8.89) N4(-13.97,-8.89) N15(13.97,-8.89) N16(16.51,-8.89) N17(19.05,-8.89) N18(21.59,-8.89) P1(-21.59,-11.43) P2(-19.05,-11.43) P3(-16.51,-11.43) P4(-13.97,-11.43) P15(13.97,-11.43) P16(16.51,-11.43) P17(19.05,-11.43) P18(21.59,-11.43) R1(-21.59,-13.97) R2(-19.05,-13.97) R3(-16.51,-13.97) R4(-13.97,-13.97) R5(-11.43,-13.97) R6(-8.89,-13.97) R7(-6.35,-13.97) R8(-3.81,-13.97) R9(-1.27,-13.97) R10(1.27,-13.97) R11(3.81,-13.97) R12(6.35,-13.97) R13(8.89,-13.97) R14(11.43,-13.97) R15(13.97,-13.97) R16(16.51,-13.97) R17(19.05,-13.97) R18(21.59,-13.97) T1(-21.59,-16.51) T2(-19.05,-16.51) T3(-16.51,-16.51) T4(-13.97,-16.51) T5(-11.43,-16.51) T6(-8.89,-16.51) T7(-6.35,-16.51) T8(-3.81,-16.51) T9(-1.27,-16.51) T10(1.27,-16.51) T11(3.81,-16.51) T12(6.35,-16.51) T13(8.89,-16.51) T14(11.43,-16.51) T15(13.97,-16.51) T16(16.51,-16.51) T17(19.05,-16.51) T18(21.59,-16.51) U1(-21.59,-19.05) U2(-19.05,-19.05) U3(-16.51,-19.05) U4(-13.97,-19.05) U5(-11.43,-19.05) U6(-8.89,-19.05) U7(-6.35,-19.05) U8(-3.81,-19.05) U9(-1.27,-19.05) U10(1.27,-19.05) U11(3.81,-19.05) U12(6.35,-19.05) U13(8.89,-19.05) U14(11.43,-19.05) U15(13.97,-19.05) U16(16.51,-19.05) U17(19.05,-19.05) U18(21.59,-19.05) V1(-21.59,-21.59) V2(-19.05,-21.59) V3(-16.51,-21.59) V4(-13.97,-21.59) V5(-11.43,-21.59) V6(-8.89,-21.59) V7(-6.35,-21.59) V8(-3.81,-21.59) V9(-1.27,-21.59) V10(1.27,-21.59) V11(3.81,-21.59) V12(6.35,-21.59) V13(8.89,-21.59) V14(11.43,-21.59) V15(13.97,-21.59) V16(16.51,-21.59) V17(19.05,-21.59) V18(21.59,-21.59)
Top Overlay:
  circle w0.25: c-24.55,21.59 r0.125
  lines w0.2: -23.9,-23.9 23.9,-23.9 23.9,23.9 -22.9,23.9 -23.9,22.9 -23.9,-23.9

## PG299 [mm] "299-Pin Ceramic Pin Grid Array (PG299)"
height 5.21
pads (299):
  round 1.5 hole 0.9: A2(-21.59,24.13) A3(-19.05,24.13) A4(-16.51,24.13) A5(-13.97,24.13) A6(-11.43,24.13) A7(-8.89,24.13) A8(-6.35,24.13) A9(-3.81,24.13) A10(-1.27,24.13) A11(1.27,24.13) A12(3.81,24.13) A13(6.35,24.13) A14(8.89,24.13) A15(11.43,24.13) A16(13.97,24.13) A17(16.51,24.13) A18(19.05,24.13) A19(21.59,24.13) A20(24.13,24.13) B1(-24.13,21.59) B2(-21.59,21.59) B3(-19.05,21.59) B4(-16.51,21.59) B5(-13.97,21.59) B6(-11.43,21.59) B7(-8.89,21.59) B8(-6.35,21.59) B9(-3.81,21.59) B10(-1.27,21.59) B11(1.27,21.59) B12(3.81,21.59) B13(6.35,21.59) B14(8.89,21.59) B15(11.43,21.59) B16(13.97,21.59) B17(16.51,21.59) B18(19.05,21.59) B19(21.59,21.59) B20(24.13,21.59) C1(-24.13,19.05) C2(-21.59,19.05) C3(-19.05,19.05) C4(-16.51,19.05) C5(-13.97,19.05) C6(-11.43,19.05) C7(-8.89,19.05) C8(-6.35,19.05) C9(-3.81,19.05) C10(-1.27,19.05) C11(1.27,19.05) C12(3.81,19.05) C13(6.35,19.05) C14(8.89,19.05) C15(11.43,19.05) C16(13.97,19.05) C17(16.51,19.05) C18(19.05,19.05) C19(21.59,19.05) C20(24.13,19.05) D1(-24.13,16.51) D2(-21.59,16.51) D3(-19.05,16.51) D4(-16.51,16.51) D5(-13.97,16.51) D6(-11.43,16.51) D7(-8.89,16.51) D8(-6.35,16.51) D9(-3.81,16.51) D10(-1.27,16.51) D11(1.27,16.51) D12(3.81,16.51) D13(6.35,16.51) D14(8.89,16.51) D15(11.43,16.51) D16(13.97,16.51) D17(16.51,16.51) D18(19.05,16.51) D19(21.59,16.51) D20(24.13,16.51) E1(-24.13,13.97) E2(-21.59,13.97) E3(-19.05,13.97) E4(-16.51,13.97) E5(-13.97,13.97) E6(-11.43,13.97) E7(-8.89,13.97) E8(-6.35,13.97) E9(-3.81,13.97) E10(-1.27,13.97) E11(1.27,13.97) E12(3.81,13.97) E13(6.35,13.97) E14(8.89,13.97) E15(11.43,13.97) E16(13.97,13.97) E17(16.51,13.97) E18(19.05,13.97) E19(21.59,13.97) E20(24.13,13.97) F1(-24.13,11.43) F2(-21.59,11.43) F3(-19.05,11.43) F4(-16.51,11.43) F5(-13.97,11.43) F16(13.97,11.43) F17(16.51,11.43) F18(19.05,11.43) F19(21.59,11.43) F20(24.13,11.43) G1(-24.13,8.89) G2(-21.59,8.89) G3(-19.05,8.89) G4(-16.51,8.89) G5(-13.97,8.89) G16(13.97,8.89) G17(16.51,8.89) G18(19.05,8.89) G19(21.59,8.89) G20(24.13,8.89) H1(-24.13,6.35) H2(-21.59,6.35) H3(-19.05,6.35) H4(-16.51,6.35) H5(-13.97,6.35) H16(13.97,6.35) H17(16.51,6.35) H18(19.05,6.35) H19(21.59,6.35) H20(24.13,6.35) J1(-24.13,3.81) J2(-21.59,3.81) J3(-19.05,3.81) J4(-16.51,3.81) J5(-13.97,3.81) J16(13.97,3.81) J17(16.51,3.81) J18(19.05,3.81) J19(21.59,3.81) J20(24.13,3.81) K1(-24.13,1.27) K2(-21.59,1.27) K3(-19.05,1.27) K4(-16.51,1.27) K5(-13.97,1.27) K16(13.97,1.27) K17(16.51,1.27) K18(19.05,1.27) K19(21.59,1.27) K20(24.13,1.27) L1(-24.13,-1.27) L2(-21.59,-1.27) L3(-19.05,-1.27) L4(-16.51,-1.27) L5(-13.97,-1.27) L16(13.97,-1.27) L17(16.51,-1.27) L18(19.05,-1.27) L19(21.59,-1.27) L20(24.13,-1.27) M1(-24.13,-3.81) M2(-21.59,-3.81) M3(-19.05,-3.81) M4(-16.51,-3.81) M5(-13.97,-3.81) M16(13.97,-3.81) M17(16.51,-3.81) M18(19.05,-3.81) M19(21.59,-3.81) M20(24.13,-3.81) N1(-24.13,-6.35) N2(-21.59,-6.35) N3(-19.05,-6.35) N4(-16.51,-6.35) N5(-13.97,-6.35) N16(13.97,-6.35) N17(16.51,-6.35) N18(19.05,-6.35) N19(21.59,-6.35) N20(24.13,-6.35) P1(-24.13,-8.89) P2(-21.59,-8.89) P3(-19.05,-8.89) P4(-16.51,-8.89) P5(-13.97,-8.89) P16(13.97,-8.89) P17(16.51,-8.89) P18(19.05,-8.89) P19(21.59,-8.89) P20(24.13,-8.89) R1(-24.13,-11.43) R2(-21.59,-11.43) R3(-19.05,-11.43) R4(-16.51,-11.43) R5(-13.97,-11.43) R16(13.97,-11.43) R17(16.51,-11.43) R18(19.05,-11.43) R19(21.59,-11.43) R20(24.13,-11.43) T1(-24.13,-13.97) T2(-21.59,-13.97) T3(-19.05,-13.97) T4(-16.51,-13.97) T5(-13.97,-13.97) T6(-11.43,-13.97) T7(-8.89,-13.97) T8(-6.35,-13.97) T9(-3.81,-13.97) T10(-1.27,-13.97) T11(1.27,-13.97) T12(3.81,-13.97) T13(6.35,-13.97) T14(8.89,-13.97) T15(11.43,-13.97) T16(13.97,-13.97) T17(16.51,-13.97) T18(19.05,-13.97) T19(21.59,-13.97) T20(24.13,-13.97) U1(-24.13,-16.51) U2(-21.59,-16.51) U3(-19.05,-16.51) U4(-16.51,-16.51) U5(-13.97,-16.51) U6(-11.43,-16.51) U7(-8.89,-16.51) U8(-6.35,-16.51) U9(-3.81,-16.51) U10(-1.27,-16.51) U11(1.27,-16.51) U12(3.81,-16.51) U13(6.35,-16.51) U14(8.89,-16.51) U15(11.43,-16.51) U16(13.97,-16.51) U17(16.51,-16.51) U18(19.05,-16.51) U19(21.59,-16.51) U20(24.13,-16.51) V1(-24.13,-19.05) V2(-21.59,-19.05) V3(-19.05,-19.05) V4(-16.51,-19.05) V5(-13.97,-19.05) V6(-11.43,-19.05) V7(-8.89,-19.05) V8(-6.35,-19.05) V9(-3.81,-19.05) V10(-1.27,-19.05) V11(1.27,-19.05) V12(3.81,-19.05) V13(6.35,-19.05) V14(8.89,-19.05) V15(11.43,-19.05) V16(13.97,-19.05) V17(16.51,-19.05) V18(19.05,-19.05) V19(21.59,-19.05) V20(24.13,-19.05) W1(-24.13,-21.59) W2(-21.59,-21.59) W3(-19.05,-21.59) W4(-16.51,-21.59) W5(-13.97,-21.59) W6(-11.43,-21.59) W7(-8.89,-21.59) W8(-6.35,-21.59) W9(-3.81,-21.59) W10(-1.27,-21.59) W11(1.27,-21.59) W12(3.81,-21.59) W13(6.35,-21.59) W14(8.89,-21.59) W15(11.43,-21.59) W16(13.97,-21.59) W17(16.51,-21.59) W18(19.05,-21.59) W19(21.59,-21.59) W20(24.13,-21.59) X1(-24.13,-24.13) X2(-21.59,-24.13) X3(-19.05,-24.13) X4(-16.51,-24.13) X5(-13.97,-24.13) X6(-11.43,-24.13) X7(-8.89,-24.13) X8(-6.35,-24.13) X9(-3.81,-24.13) X10(-1.27,-24.13) X11(1.27,-24.13) X12(3.81,-24.13) X13(6.35,-24.13) X14(8.89,-24.13) X15(11.43,-24.13) X16(13.97,-24.13) X17(16.51,-24.13) X18(19.05,-24.13) X19(21.558,-24.142) X20(24.13,-24.13)
Top Overlay:
  circle w0.25: c-27.1,24.13 r0.125
  lines w0.2: -26.45,-26.45 26.45,-26.45 26.45,26.45 -25.45,26.45 -26.45,25.45 -26.45,-26.45

## PG411 [mm] "411-Pin Ceramic Pin Grid Array (PG411)"
height 5.86
pads (411):
  round 1.5 hole 0.9: A3(-21.59,24.13) A5(-19.05,24.13) A7(-16.51,24.13) A9(-13.97,24.13) A11(-11.43,24.13) A13(-8.89,24.13) A15(-6.35,24.13) A17(-3.81,24.13) A19(-1.27,24.13) A21(1.27,24.13) A23(3.81,24.13) A25(6.35,24.13) A27(8.89,24.13) A29(11.43,24.13) A31(13.97,24.13) A33(16.51,24.13) A35(19.05,24.13) A37(21.59,24.13) A39(24.13,24.13) AA1(-24.13,-1.27) AA3(-21.59,-1.27) AA5(-19.05,-1.27) AA35(19.05,-1.27) AA37(21.59,-1.27) AA39(24.13,-1.27) AB2(-22.86,-2.54) AB4(-20.32,-2.54) AB6(-17.78,-2.54) AB34(17.78,-2.54) AB36(20.32,-2.54) AB38(22.86,-2.54) AC1(-24.13,-3.81) AC3(-21.59,-3.81) AC5(-19.05,-3.81) AC35(19.05,-3.81) AC37(21.59,-3.81) AC39(24.13,-3.81) AD2(-22.86,-5.08) AD4(-20.32,-5.08) AD6(-17.78,-5.08) AD34(17.78,-5.08) AD36(20.32,-5.08) AD38(22.86,-5.08) AE1(-24.13,-6.35) AE3(-21.59,-6.35) AE5(-19.05,-6.35) AE35(19.05,-6.35) AE37(21.59,-6.35) AE39(24.13,-6.35) AF2(-22.86,-7.62) AF4(-20.32,-7.62) AF6(-17.78,-7.62) AF34(17.78,-7.62) AF36(20.32,-7.62) AF38(22.86,-7.62) AG1(-24.13,-8.89) AG3(-21.59,-8.89) AG5(-19.05,-8.89) AG35(19.05,-8.89) AG37(21.59,-8.89) AG39(24.13,-8.89) AH2(-22.86,-10.16) AH4(-20.32,-10.16) AH6(-17.78,-10.16) AH34(17.78,-10.16) AH36(20.32,-10.16) AH38(22.86,-10.16) AJ1(-24.13,-11.43) AJ3(-21.59,-11.43) AJ5(-19.05,-11.43) AJ35(19.05,-11.43) AJ37(21.59,-11.43) AJ39(24.13,-11.43) AK2(-22.86,-12.7) AK4(-20.32,-12.7) AK6(-17.78,-12.7) AK34(17.78,-12.7) AK36(20.32,-12.7) AK38(22.86,-12.7) AL1(-24.13,-13.97) AL3(-21.59,-13.97) AL5(-19.05,-13.97) AL7(-16.51,-13.97) AL33(16.51,-13.97) AL35(19.05,-13.97) AL37(21.59,-13.97) AL39(24.13,-13.97) AM2(-22.86,-15.24) AM4(-20.32,-15.24) AM6(-17.78,-15.24) AM8(-15.24,-15.24) AM32(15.24,-15.24) AM34(17.78,-15.24) AM36(20.32,-15.24) AM38(22.86,-15.24) AN1(-24.13,-16.51) AN3(-21.59,-16.51) AN5(-19.05,-16.51) AN7(-16.51,-16.51) AN9(-13.97,-16.51) AN31(13.97,-16.51) AN33(16.51,-16.51) AN35(19.05,-16.51) AN37(21.59,-16.51) AN39(24.13,-16.51) AP2(-22.86,-17.78) AP4(-20.32,-17.78) AP6(-17.78,-17.78) AP8(-15.24,-17.78) AP10(-12.7,-17.78) AP12(-10.16,-17.78) AP14(-7.62,-17.78) AP16(-5.08,-17.78) AP18(-2.54,-17.78) AP20(0,-17.78) AP22(2.54,-17.78) AP24(5.08,-17.78) AP26(7.62,-17.78) AP28(10.16,-17.78) AP30(12.7,-17.78) AP32(15.24,-17.78) AP34(17.78,-17.78) AP36(20.32,-17.78) AP38(22.86,-17.78) AR1(-24.13,-19.05) AR3(-21.59,-19.05) AR5(-19.05,-19.05) AR7(-16.51,-19.05) AR9(-13.97,-19.05) AR11(-11.43,-19.05) AR13(-8.89,-19.05) AR15(-6.35,-19.05) AR17(-3.81,-19.05) AR19(-1.27,-19.05) AR21(1.27,-19.05) AR23(3.81,-19.05) AR25(6.35,-19.05) AR27(8.89,-19.05) AR29(11.43,-19.05) AR31(13.97,-19.05) AR33(16.51,-19.05) AR35(19.05,-19.05) AR37(21.59,-19.05) AR39(24.13,-19.05) AT2(-22.86,-20.32) AT4(-20.32,-20.32) AT6(-17.78,-20.32) AT8(-15.24,-20.32) AT10(-12.7,-20.32) AT12(-10.16,-20.32) AT14(-7.62,-20.32) AT16(-5.08,-20.32) AT18(-2.54,-20.32) AT20(0,-20.32) AT22(2.54,-20.32) AT24(5.08,-20.32) AT26(7.62,-20.32) AT28(10.16,-20.32) AT30(12.7,-20.32) AT32(15.24,-20.32) AT34(17.78,-20.32) AT36(20.32,-20.32) AT38(22.86,-20.32) AU1(-24.13,-21.59) AU3(-21.59,-21.59) AU5(-19.05,-21.59) AU7(-16.51,-21.59) AU9(-13.97,-21.59) AU11(-11.43,-21.59) AU13(-8.89,-21.59) AU15(-6.35,-21.59) AU17(-3.81,-21.59) AU19(-1.27,-21.59) AU21(1.27,-21.59) AU23(3.81,-21.59) AU25(6.35,-21.59) AU27(8.89,-21.59) AU29(11.43,-21.59) AU31(13.97,-21.59) AU33(16.51,-21.59) AU35(19.05,-21.59) AU37(21.59,-21.59) AU39(24.13,-21.59) AV2(-22.86,-22.86) AV4(-20.32,-22.86) AV6(-17.78,-22.86) AV8(-15.24,-22.86) AV10(-12.7,-22.86) AV12(-10.16,-22.86) AV14(-7.62,-22.86) AV16(-5.08,-22.86) AV18(-2.54,-22.86) AV20(0,-22.86) AV22(2.54,-22.86) AV24(5.08,-22.86) AV26(7.62,-22.86) AV28(10.16,-22.86) AV30(12.7,-22.86) AV32(15.24,-22.86) AV34(17.78,-22.86) AV36(20.32,-22.86) AV38(22.86,-22.86) AW1(-24.13,-24.13) AW3(-21.59,-24.13) AW5(-19.05,-24.13) AW7(-16.51,-24.13) AW9(-13.97,-24.13) AW11(-11.43,-24.13) AW13(-8.89,-24.13) AW15(-6.35,-24.13) AW17(-3.81,-24.13) AW19(-1.27,-24.13) AW21(1.27,-24.13) AW23(3.81,-24.13) AW25(6.35,-24.13) AW27(8.89,-24.13) AW29(11.43,-24.13) AW31(13.97,-24.13) AW33(16.51,-24.13) AW35(19.05,-24.13) AW37(21.59,-24.13) AW39(24.13,-24.13) B2(-22.86,22.86) B4(-20.32,22.86) B6(-17.78,22.86) B8(-15.24,22.86) B10(-12.7,22.86) B12(-10.16,22.86) B14(-7.62,22.86) B16(-5.08,22.86) B18(-2.54,22.86) B20(0,22.86) B22(2.54,22.86) B24(5.08,22.86) B26(7.62,22.86) B28(10.16,22.86) B30(12.7,22.86) B32(15.24,22.86) B34(17.78,22.86) B36(20.32,22.86) B38(22.86,22.86) C1(-24.13,21.59) C3(-21.59,21.59) C5(-19.05,21.59) C7(-16.51,21.59) C9(-13.97,21.59) C11(-11.43,21.59) C13(-8.89,21.59) C15(-6.35,21.59) C17(-3.81,21.59) C19(-1.27,21.59) C21(1.27,21.59) C23(3.81,21.59) C25(6.35,21.59) C27(8.89,21.59) C29(11.43,21.59) C31(13.97,21.59) C33(16.51,21.59) C35(19.05,21.59) C37(21.59,21.59) C39(24.13,21.59) D2(-22.86,20.32) D4(-20.32,20.32) D6(-17.78,20.32) D8(-15.24,20.32) D10(-12.7,20.32) D12(-10.16,20.32) D14(-7.62,20.32) D16(-5.08,20.32) D18(-2.54,20.32) D20(0,20.32) D22(2.54,20.32) D24(5.08,20.32) D26(7.62,20.32) D28(10.16,20.32) D30(12.7,20.32) D32(15.24,20.32) D34(17.78,20.32) D36(20.32,20.32) D38(22.86,20.32) E1(-24.13,19.05) E3(-21.59,19.05) E5(-19.05,19.05) E7(-16.51,19.05) E9(-13.97,19.05) E11(-11.43,19.05) E13(-8.89,19.05) E15(-6.35,19.05) E17(-3.81,19.05) E19(-1.27,19.05) E21(1.27,19.05) E23(3.81,19.05) E25(6.35,19.05) E27(8.89,19.05) E29(11.43,19.05) E31(13.97,19.05) E33(16.51,19.05) E35(19.05,19.05) E37(21.59,19.05) E39(24.13,19.05) F2(-22.86,17.78) F4(-20.32,17.78) F6(-17.78,17.78) F8(-15.24,17.78) F10(-12.7,17.78) F12(-10.16,17.78) F14(-7.62,17.78) F16(-5.08,17.78) F18(-2.54,17.78) F20(0,17.78) F22(2.54,17.78) F24(5.08,17.78) F26(7.62,17.78) F28(10.16,17.78) F30(12.7,17.78) F32(15.24,17.78) F34(17.78,17.78) F36(20.32,17.78) F38(22.86,17.78) G1(-24.13,16.51) G3(-21.59,16.51) G5(-19.05,16.51) G7(-16.51,16.51) G9(-13.97,16.51) G31(13.97,16.51) G33(16.51,16.51) G35(19.05,16.51) G37(21.59,16.51) G39(24.13,16.51) H2(-22.86,15.24) H4(-20.32,15.24) H6(-17.78,15.24) H8(-15.24,15.24) H32(15.24,15.24) H34(17.78,15.24) H36(20.32,15.24) H38(22.86,15.24) J1(-24.13,13.97) J3(-21.59,13.97) J5(-19.05,13.97) J7(-16.51,13.97) J33(16.51,13.97) J35(19.05,13.97) J37(21.59,13.97) J39(24.13,13.97) K2(-22.86,12.7) K4(-20.32,12.7) K6(-17.78,12.7) K34(17.78,12.7) K36(20.32,12.7) K38(22.86,12.7) L1(-24.13,11.43) L3(-21.59,11.43) L5(-19.05,11.43) L35(19.05,11.43) L37(21.59,11.43) L39(24.13,11.43) M2(-22.86,10.16) M4(-20.32,10.16) M6(-17.78,10.16) M34(17.78,10.16) M36(20.32,10.16) M38(22.86,10.16) N1(-24.13,8.89) N3(-21.59,8.89) N5(-19.05,8.89) N35(19.05,8.89) N37(21.59,8.89) N39(24.13,8.89) P2(-22.86,7.62) P4(-20.32,7.62) P6(-17.78,7.62) P34(17.78,7.62) P36(20.32,7.62) P38(22.86,7.62) R1(-24.13,6.35) R3(-21.59,6.35) R5(-19.05,6.35) R35(19.05,6.35) R37(21.59,6.35) R39(24.13,6.35) T2(-22.86,5.08) T4(-20.32,5.08) T6(-17.78,5.08) T34(17.78,5.08) T36(20.32,5.08) T38(22.86,5.08) U1(-24.13,3.81) U3(-21.59,3.81) U5(-19.05,3.81) U35(19.05,3.81) U37(21.59,3.81) U39(24.13,3.81) V2(-22.86,2.54) V4(-20.32,2.54) V6(-17.78,2.54) V34(17.78,2.54) V36(20.32,2.54) V38(22.86,2.54) W1(-24.13,1.27) W3(-21.59,1.27) W5(-19.05,1.27) W35(19.05,1.27) W37(21.59,1.27) W39(24.13,1.27) Y2(-22.86,0) Y4(-20.32,0) Y6(-17.78,0) Y34(17.78,0) Y36(20.32,0) Y38(22.86,0)
Top Overlay:
  circle w0.25: c-27.1,24.13 r0.125
  lines w0.2: -26.45,-26.45 -26.45,25.45 -25.45,26.45 26.45,26.45 26.45,-26.45 -26.45,-26.45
